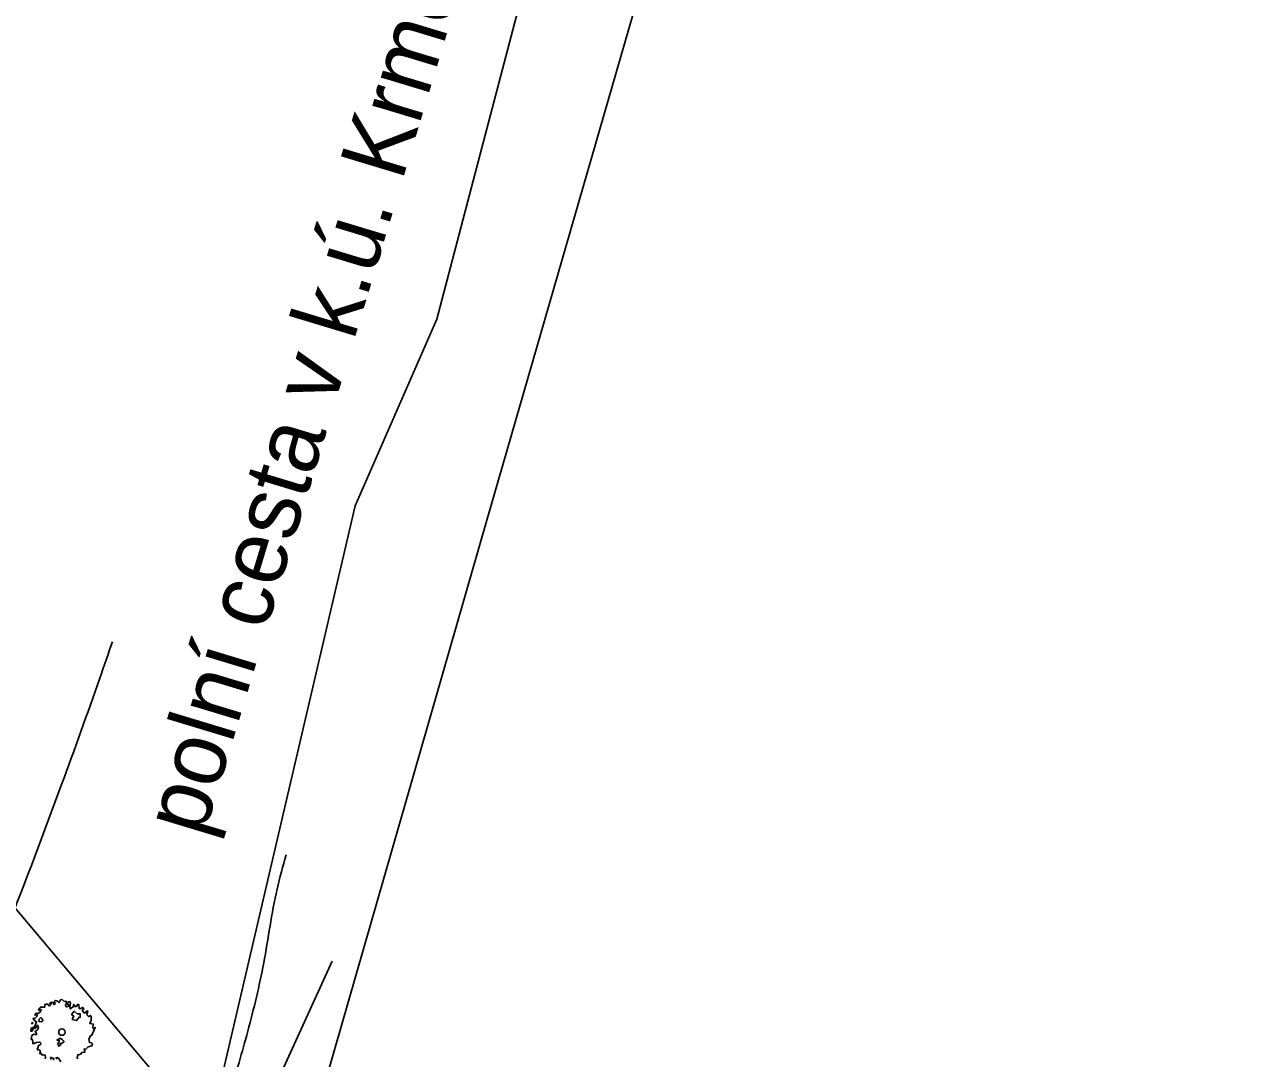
# Model space of a CAD drawing. Extents: x -475575 to -473225, y -1116053 to -1114104.
# Drawn here: x -474334.3 to -474241.7, y -1114439 to -1114360.5 of the extents above; entities that cross this region are included whole.
import ezdxf

# ---------------------------------------------------------------- set-up
doc = ezdxf.new("R2010")
doc.units = 0
for name, color, linetype in [('IP', 7, 'Continuous'), ('TP_HS', 7, 'Continuous'), ('Vrstevnice_hlavni', 7, 'Continuous'), ('Vrstevnice_vedlejsi', 7, 'Continuous'), ('Vrstva 10', 7, 'Continuous'), ('Vrstva_10', 7, 'Continuous')]:
    doc.layers.add(name, color=color, linetype=linetype)

msp = doc.modelspace()

# ---------------------------------------------------------------- linework, layer by layer
msp.add_lwpolyline([(-474392.24, -1114354.32), (-474385.18, -1114363.49), (-474350.25, -1114409.55), (-474320.41, -1114444.98), (-474314.65, -1114451.82), (-474310.64, -1114456.39), (-474234.21, -1114527.12), (-474221.34, -1114539.99), (-474214.34, -1114543), (-474154.82, -1114540.65), (-474095.35, -1114551.68), (-474072.2, -1114553.97), (-474025.99, -1114569.87)])
at = {"layer": 'IP'}
for points in [[(-474332.748, -1114439.059), (-474332.711, -1114438.953), (-474332.741, -1114438.776), (-474332.882, -1114438.741), (-474332.966, -1114438.766), (-474333.065, -1114438.614), (-474333.156, -1114438.662), (-474333.127, -1114438.454), (-474333.186, -1114438.366), (-474333.289, -1114438.378), (-474333.344, -1114438.247), (-474333.275, -1114438.228), (-474333.287, -1114438.147), (-474333.267, -1114438.058), (-474333.231, -1114438.021), (-474333.166, -1114438.002), (-474333.11, -1114437.955), (-474333.072, -1114437.898), (-474333.102, -1114437.817), (-474333.204, -1114437.788), (-474333.424, -1114437.802), (-474333.588, -1114437.888), (-474333.693, -1114437.887), (-474333.676, -1114437.703), (-474333.729, -1114437.576), (-474333.81, -1114437.551), (-474333.768, -1114437.275), (-474333.702, -1114437.247), (-474333.611, -1114437.179), (-474333.41, -1114437.22), (-474333.41, -1114437.121), (-474333.508, -1114436.972), (-474333.357, -1114436.863), (-474333.26, -1114436.69), (-474333.317, -1114436.491), (-474333.521, -1114436.761), (-474333.543, -1114436.626), (-474333.394, -1114436.237), (-474333.534, -1114436.165), (-474333.646, -1114436.004), (-474333.629, -1114435.957), (-474333.522, -1114435.998), (-474333.334, -1114435.776), (-474333.384, -1114435.683), (-474333.539, -1114435.732), (-474333.436, -1114435.575), (-474333.305, -1114435.6), (-474333.136, -1114435.497), (-474333.055, -1114435.281), (-474333.221, -1114435.36), (-474333.25, -1114435.283), (-474333.07, -1114435.09), (-474333.079, -1114435.126), (-474332.783, -1114435.119), (-474332.775, -1114434.936), (-474332.649, -1114434.888), (-474332.53, -1114434.902), (-474332.498, -1114435.004), (-474332.425, -1114435.028), (-474332.284, -1114434.867), (-474332.409, -1114434.854), (-474332.273, -1114434.751), (-474332.137, -1114434.778), (-474332.076, -1114434.927), (-474331.985, -1114434.874), (-474332.041, -1114434.684), (-474331.952, -1114434.623), (-474331.812, -1114434.672), (-474331.69, -1114434.781), (-474331.577, -1114434.56), (-474331.455, -1114434.556), (-474331.315, -1114434.688), (-474331.162, -1114434.662), (-474331.13, -1114434.768), (-474331.208, -1114434.965), (-474331.149, -1114435.106), (-474330.992, -1114435.07), (-474330.918, -1114434.928), (-474331.001, -1114434.945), (-474331.043, -1114434.88), (-474331.068, -1114434.791), (-474330.92, -1114434.708), (-474330.827, -1114434.766), (-474330.841, -1114434.993), (-474330.886, -1114435.074), (-474330.845, -1114435.263), (-474330.839, -1114435.243), (-474330.6, -1114435.085), (-474330.591, -1114434.92), (-474330.455, -1114435.099), (-474330.337, -1114435.053), (-474330.291, -1114434.916), (-474330.193, -1114434.912), (-474330.153, -1114435.236), (-474329.994, -1114435.231), (-474329.923, -1114435.136), (-474329.818, -1114435.291), (-474329.914, -1114435.367), (-474329.872, -1114435.501), (-474329.743, -1114435.573), (-474329.606, -1114435.421), (-474329.519, -1114435.413), (-474329.53, -1114435.55), (-474329.571, -1114435.623), (-474329.557, -1114435.743), (-474329.466, -1114435.844), (-474329.313, -1114435.757), (-474329.248, -1114435.817), (-474329.259, -1114436.129), (-474329.364, -1114436.366), (-474329.09, -1114436.406), (-474329.13, -1114436.618), (-474329.103, -1114436.763), (-474328.942, -1114436.658), (-474329.199, -1114437.255), (-474329.356, -1114437.336), (-474329.353, -1114437.465), (-474329.426, -1114437.498), (-474329.416, -1114437.678), (-474329.38, -1114437.813), (-474329.221, -1114437.831), (-474329.145, -1114437.913), (-474329.214, -1114438.074), (-474329.495, -1114438.126), (-474329.681, -1114438.348), (-474329.797, -1114438.296), (-474329.735, -1114438.537), (-474329.978, -1114438.571), (-474329.999, -1114438.661), (-474330.218, -1114438.74), (-474330.271, -1114438.743), (-474330.317, -1114438.978), (-474330.274, -1114439.041)], [(-474332.108, -1114439.141), (-474332.076, -1114439.029), (-474332.294, -1114438.942), (-474332.33, -1114438.935), (-474332.321, -1114439.089)], [(-474331.562, -1114439.277), (-474331.713, -1114439.029), (-474331.834, -1114438.94), (-474331.927, -1114438.964), (-474331.843, -1114439.056)]]:
    msp.add_lwpolyline(points, dxfattribs=at)
for points in [[(-474330.696, -1114436.053), (-474330.361, -1114436.143), (-474330.139, -1114435.866), (-474330.082, -1114435.911), (-474330.096, -1114435.622), (-474330.316, -1114435.632), (-474330.552, -1114435.44), (-474330.744, -1114435.676), (-474330.564, -1114435.822), (-474330.654, -1114435.933)], [(-474333.748, -1114436.421), (-474333.675, -1114436.34), (-474333.716, -1114436.295), (-474333.749, -1114436.321)], [(-474333.214, -1114436.226), (-474333.056, -1114436.242), (-474332.912, -1114436.154), (-474332.973, -1114436.02), (-474333.084, -1114435.918), (-474333.213, -1114436.041)], [(-474333.744, -1114436.948), (-474333.644, -1114436.763), (-474333.638, -1114436.647), (-474333.786, -1114436.732), (-474333.812, -1114436.702), (-474333.83, -1114436.951)], [(-474331.651, -1114437.894), (-474331.508, -1114437.884), (-474331.316, -1114437.741), (-474331.423, -1114437.597), (-474331.607, -1114437.482), (-474331.858, -1114437.623), (-474331.68, -1114437.641), (-474331.69, -1114437.745), (-474331.753, -1114437.845), (-474331.781, -1114437.889), (-474331.745, -1114438.075), (-474331.652, -1114438.057), (-474331.579, -1114438.001), (-474331.614, -1114437.931)]]:
    msp.add_lwpolyline(points, close=True, dxfattribs=at)
msp.add_circle((-474331.473, -1114437.017), 0.247, dxfattribs=at)
at = {"layer": 'Vrstevnice_hlavni'}
msp.add_spline([(-474314.465, -1114423.562), (-474315.15, -1114426.169), (-474316.163, -1114431.774), (-474317.369, -1114436.945), (-474318.766, -1114441.68), (-474320.354, -1114445.981), (-474321.972, -1114449.681), (-474323.617, -1114452.78), (-474325.291, -1114455.277), (-474326.741, -1114457.93), (-474327.967, -1114460.736), (-474328.969, -1114463.698), (-474329.844, -1114466.14), (-474330.593, -1114468.063), (-474331.215, -1114469.466), (-474332.084, -1114471.237), (-474333.198, -1114473.375), (-474334.559, -1114475.88), (-474336.125, -1114478.272), (-474337.896, -1114480.55), (-474339.872, -1114482.714), (-474341.606, -1114484.471), (-474343.097, -1114485.82), (-474344.345, -1114486.761), (-474345.399, -1114487.69), (-474346.258, -1114488.605), (-474346.922, -1114489.508), (-474348.744, -1114492.982), (-474351.724, -1114499.027), (-474355.862, -1114507.643), (-474358.802, -1114513.52), (-474360.543, -1114516.658), (-474361.086, -1114517.057), (-474361.549, -1114517.367), (-474361.932, -1114517.589), (-474362.234, -1114517.723), (-474362.692, -1114518.027), (-474363.306, -1114518.501), (-474364.075, -1114519.145), (-474364.359, -1114519.998), (-474364.157, -1114521.059), (-474363.469, -1114522.329), (-474364.041, -1114525.543), (-474365.872, -1114530.7), (-474368.962, -1114537.801), (-474371.03, -1114542.537), (-474372.077, -1114544.908), (-474372.101, -1114544.915), (-474372.13, -1114544.928), (-474372.164, -1114544.948), (-474372.202, -1114544.975), (-474373.035, -1114545.505), (-474374.661, -1114546.538), (-474377.082, -1114548.074), (-474379.165, -1114549.699), (-474380.91, -1114551.414), (-474382.317, -1114553.219), (-474383.093, -1114555.278), (-474383.239, -1114557.591), (-474382.271, -1114562.728)], degree=3, dxfattribs=at)
at = {"layer": 'Vrstevnice_vedlejsi'}
msp.add_spline([(-474327.641, -1114407.394), (-474328.603, -1114410.163), (-474331.498, -1114418.235), (-474335.644, -1114429.118), (-474339.003, -1114437.261), (-474341.575, -1114442.664), (-474343.361, -1114445.328), (-474344.701, -1114447.548), (-474345.596, -1114449.324), (-474346.047, -1114450.656), (-474347.707, -1114454.61), (-474350.577, -1114461.188), (-474354.656, -1114470.389), (-474357.396, -1114476.561), (-474358.797, -1114479.703), (-474358.858, -1114479.815), (-474358.928, -1114479.922), (-474359.008, -1114480.025), (-474359.096, -1114480.122), (-474359.174, -1114480.201), (-474359.241, -1114480.261), (-474359.297, -1114480.304), (-474359.345, -1114480.345), (-474359.383, -1114480.386), (-474359.413, -1114480.427), (-474359.495, -1114480.583), (-474359.629, -1114480.854), (-474359.814, -1114481.241), (-474361.795, -1114482.862), (-474365.571, -1114485.716), (-474371.143, -1114489.805), (-474375.891, -1114492.988), (-474379.817, -1114495.267), (-474382.92, -1114496.64), (-474386.819, -1114499.089), (-474391.515, -1114502.613), (-474397.008, -1114507.212), (-474401.449, -1114508.322), (-474404.838, -1114505.943), (-474407.175, -1114500.076), (-474409.173, -1114494.493), (-474410.831, -1114489.194), (-474412.149, -1114484.18), (-474412.82, -1114480.198), (-474412.846, -1114477.248), (-474412.226, -1114475.331), (-474411.8, -1114474.019), (-474411.568, -1114473.315), (-474411.531, -1114473.216), (-474411.527, -1114473.077), (-474411.557, -1114472.897), (-474411.62, -1114472.676), (-474411.726, -1114472.437), (-474411.876, -1114472.179), (-474412.069, -1114471.903), (-474414.084, -1114468.235), (-474417.923, -1114461.176), (-474423.583, -1114450.725), (-474427.711, -1114443.268), (-474430.305, -1114438.804), (-474431.366, -1114437.334), (-474432.27, -1114436.107), (-474433.015, -1114435.123), (-474433.603, -1114434.383), (-474434.851, -1114432.753), (-474436.762, -1114430.233)], degree=3, dxfattribs=at)
at = {"layer": 'Vrstva 10'}
msp.add_lwpolyline([(-474320.412, -1114444.978), (-474314.65, -1114451.82), (-474299.295, -1114398.345), (-474282.356, -1114339.747), (-474269.831, -1114316.275), (-474245.148, -1114261.154), (-474252.42, -1114259.83), (-474273.03, -1114302.54), (-474292.982, -1114343.986), (-474295.83, -1114355.43), (-474303.03, -1114382.92), (-474309.23, -1114397.09)], close=True, dxfattribs=at)
at = {"layer": 'Vrstva_10'}
msp.add_lwpolyline([(-474333.027, -1114502.62), (-474332.577, -1114494.663), (-474330.866, -1114487.83), (-474328.997, -1114477.921), (-474326.996, -1114469.3), (-474323.692, -1114459.536), (-474310.981, -1114431.627)], dxfattribs=at)

# ---------------------------------------------------------------- texts
at = {"layer": 'TP_HS'}
msp.add_text('polní cesta v k.ú. Krmelín', height=5, rotation=73.16187, dxfattribs=at).set_placement((-474320.745, -1114422.329))

doc.saveas('drawing.dxf')
